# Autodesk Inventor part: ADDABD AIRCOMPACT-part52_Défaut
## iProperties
Shininess: 64.0
Length Units: 11269
Angle Units: 11279
Time Units: 11290
Mass Units: 11283
Length Display Precision: 3
Angle Display Precision: 2
Compacted: True
Part Number: ADDABD AIRCOMPACT-part52_Défaut
Document SubType Name: Modeling
Created: 2006-01
Material: Par défaut
Designer: riri
Density: 0.0
Volumn: 0.0
Area: 0.0
PropertySet Name: Model Information
Control State: 0
Master: False
Checked Out: False
Author: riri
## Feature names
1. Base1
